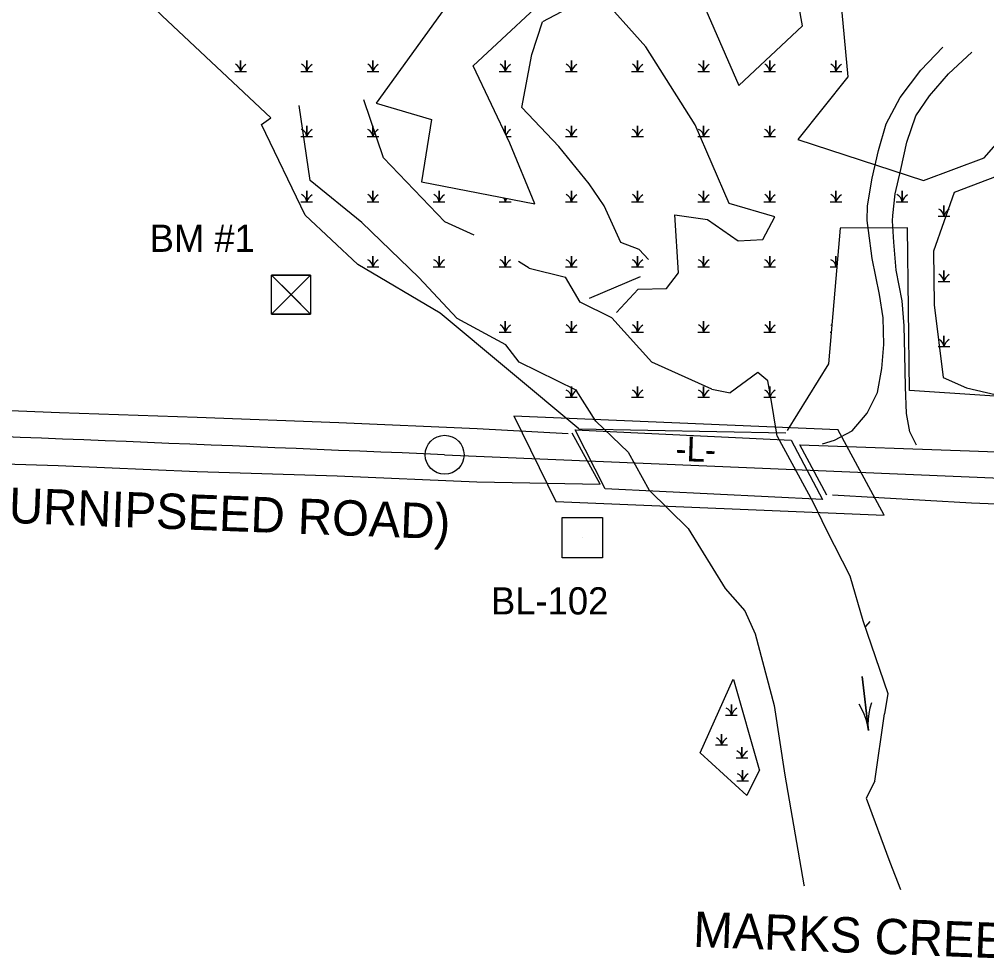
# Model space of a CAD drawing. Extents: x 2169223 to 2172151, y 723262 to 725175.
# Drawn here: x 2170758.3 to 2171113.8, y 723889.2 to 724234.9 of the extents above; entities that cross this region are included whole.
import ezdxf

# ---------------------------------------------------------------- set-up
doc = ezdxf.new("R2010")
doc.units = 0
for name, color, linetype in [('COGO Default Chain', 7, 'Continuous'), ('CTL Bench Mark CELL', 7, 'Continuous'), ('CTL Bench Mark Text', 7, 'Continuous'), ('CTL Supplemental Horizontal and Vertical CELL', 7, 'Continuous'), ('CTL Supplemental Horizontal and Vertical Text', 7, 'Continuous'), ('Default', 7, 'Continuous'), ('Exist Hydro Jurisdictional Stream or Body of Water', 7, 'Continuous'), ('Exist Hydro Pool or Reservoir', 7, 'Continuous'), ('Exist Hydro River Flow Arrow CELL', 7, 'Continuous'), ('Exist Roads EOP', 7, 'Continuous'), ('Exist Roads EOP Other', 7, 'Continuous'), ('Exist Structure Major Deck Tunnel Box Culvert', 7, 'Continuous'), ('Old_Level_12', 7, 'Continuous'), ('Prop Horizontal Alignment', 7, 'Continuous'), ('Prop Horizontal Alignment Direction Label', 7, 'Continuous'), ('Prop Horizontal Alignment Station Label', 7, 'Continuous')]:
    doc.layers.add(name, color=color, linetype=linetype)

# ---------------------------------------------------------------- blocks, each defined once
blk = doc.blocks.new('EXIST HYDRO RIVER FLOW ARROW')
at = {"layer": 'Exist Hydro River Flow Arrow CELL'}
blk.add_line((0, 0), (0, 0), dxfattribs=at)
blk.add_lwpolyline([(0, 0.04575), (0.03775, 0.03), (0.07725, 0.01725), (0.118, 0.00775), (0.159, 0.0015), (0.2, 0), (-0.2, 0), (0.2, 0), (0.159, -0.0015), (0.118, -0.00775), (0.07725, -0.01725), (0.03775, -0.03), (0, -0.04575)], dxfattribs=at)
blk = doc.blocks.new('Exist Hydro Swamp or Marsh')
at = {"layer": 'Default'}
blk.add_line((0, 0), (0, 0), dxfattribs=at)
blk.add_lwpolyline([(-0.043, -0.0357), (0, -0.0357), (0, 0.0432), (0, -0.0357), (0.043, -0.0357)], dxfattribs=at)
for centre, radius, start, end in [((-0.0613, -0.0401), 0.0615, 4.14034, 67.53497), ((0.0912, -0.066), 0.0961, 122.12745, 161.62219)]:
    blk.add_arc(centre, radius, start, end, dxfattribs=at)
blk = doc.blocks.new('CTL BENCH MARK')
at = {"layer": 'CTL Bench Mark CELL'}
blk.add_line((0, 0), (0, 0), dxfattribs=at)
blk.add_lwpolyline([(-0.072, 0.07175), (0.07175, 0.07175), (0.07175, -0.072), (-0.072, -0.072)], close=True, dxfattribs=at)
for points in [[(0.07175, 0.07175), (-0.072, -0.072), (-0.000125, -0.000125), (0.07175, -0.072), (-0.072, 0.07175)], [(-0.000125, -0.000125), (0.07175, 0.07175), (-0.072, 0.07175), (-0.000125, -0.000125)], [(-0.000125, -0.000125), (-0.072, -0.072), (0.07175, -0.072), (-0.000125, -0.000125)]]:
    blk.add_lwpolyline(points, dxfattribs=at)
blk = doc.blocks.new('CTL SUPPLEMENTAL HORIZONTAL AND VERTICAL')
at = {"layer": 'CTL Supplemental Horizontal and Vertical CELL'}
blk.add_line((0, 0), (0, 0), dxfattribs=at)
blk.add_lwpolyline([(-0.0735, 0.074), (0.07475, 0.074), (0.07475, -0.0745), (-0.0735, -0.0745)], close=True, dxfattribs=at)

msp = doc.modelspace()

# ---------------------------------------------------------------- linework, layer by layer
at = {"layer": 'COGO Default Chain'}
msp.add_lwpolyline([(2171039.94, 724084.11), (2171039.94, 724084.11), (2171039.94, 724084.11), (2171039.94, 724084.11), (2171039.94, 724084.11)], dxfattribs=at)
at = {"layer": 'Default'}
for p, q in [((2170940.05, 724089.16), (2171059.1, 724084.14)), ((2170940.05, 724089.16), (2170955.48, 724057.65)), ((2170964, 724084.29), (2171040, 724082.92)), ((2171076.21, 724052.56), (2171059.1, 724084.14)), ((2170955.48, 724057.65), (2171076.21, 724052.56)), ((2171020.86, 723992.13), (2171020.86, 723992.13)), ((2171030.33, 723958.99), (2171020.86, 723992.13))]:
    msp.add_line(p, q, dxfattribs=at)
for points in [[(2171646.71, 724409.08), (2171639.12, 724404.07), (2171615.95, 724359.66), (2171585.14, 724346.96), (2171572.27, 724330.12), (2171541.38, 724278.6), (2171494.05, 724272.59), (2171450.52, 724247.37), (2171445.92, 724243.67), (2171427.74, 724238.82), (2171406.38, 724186.3), (2171401.13, 724168.54), (2171393.3, 724167.45), (2171368.95, 724149.15), (2171363.45, 724127.38), (2171338.31, 724101.83), (2171299.81, 724093.74), (2171257.11, 724087.08), (2171085.47, 724098.48), (2171084.69, 724158.24), (2171059.94, 724158.08), (2171055.72, 724108.27), (2171040.51, 724083.75)], [(2170969.77, 724384.57), (2170964.6, 724352.67), (2170972.04, 724333.24), (2170983.7, 724287.77), (2170949.07, 724287.96), (2170925.23, 724253.71), (2170889.53, 724203.99), (2170909.76, 724198.04), (2170906.17, 724175.12), (2170947.8, 724166.99), (2170938.58, 724189.31), (2170925.06, 724217.79), (2170958.31, 724248.78), (2170980.13, 724250.58), (2170999.41, 724264.35), (2171022.73, 724210.59), (2171046.16, 724232.49), (2171037.9, 724278.23), (2171056.23, 724284.73), (2171062.81, 724213.77), (2171044.44, 724190.74), (2171090.65, 724175.58), (2171112.89, 724183.96), (2171129.39, 724202.76)], [(2170964, 724084.29), (2170912.98, 724126.85), (2170882.79, 724144.74), (2170863.38, 724162.92), (2170847.33, 724196.18), (2170850.8, 724198.69), (2170810.88, 724236.14), (2170789.38, 724258.53), (2170787.06, 724316.72), (2170767.72, 724349.95)], [(2170837.48, 724215.73), (2170839.63, 724215.73), (2170839.63, 724219.67), (2170839.63, 724215.73), (2170841.78, 724215.73)], [(2170861.8, 724215.73), (2170863.95, 724215.73), (2170863.95, 724219.67), (2170863.95, 724215.73), (2170866.1, 724215.73)], [(2170886.11, 724215.73), (2170888.26, 724215.73), (2170888.26, 724219.67), (2170888.26, 724215.73), (2170890.41, 724215.73)], [(2170934.73, 724215.73), (2170936.88, 724215.73), (2170936.88, 724219.67), (2170936.88, 724215.73), (2170939.03, 724215.73)], [(2170959.05, 724215.73), (2170961.2, 724215.73), (2170961.2, 724219.67), (2170961.2, 724215.73), (2170963.35, 724215.73)], [(2170983.36, 724215.73), (2170985.51, 724215.73), (2170985.51, 724219.67), (2170985.51, 724215.73), (2170987.66, 724215.73)], [(2171007.67, 724215.73), (2171009.82, 724215.73), (2171009.82, 724219.67), (2171009.82, 724215.73), (2171011.97, 724215.73)], [(2171031.98, 724215.73), (2171034.13, 724215.73), (2171034.13, 724219.67), (2171034.13, 724215.73), (2171036.28, 724215.73)], [(2171056.3, 724215.73), (2171058.45, 724215.73), (2171058.45, 724219.67), (2171058.45, 724215.73), (2171060.6, 724215.73)], [(2170861.8, 724191.78), (2170863.95, 724191.78), (2170863.95, 724195.72), (2170863.95, 724191.78), (2170866.1, 724191.78)], [(2170886.11, 724191.78), (2170888.26, 724191.78), (2170888.26, 724195.72), (2170888.26, 724191.78), (2170890.41, 724191.78)], [(2170936.88, 724192.89), (2170936.88, 724195.72), (2170936.88, 724192.89)], [(2170959.05, 724191.78), (2170961.2, 724191.78), (2170961.2, 724195.72), (2170961.2, 724191.78), (2170963.35, 724191.78)], [(2170983.36, 724191.78), (2170985.51, 724191.78), (2170985.51, 724195.72), (2170985.51, 724191.78), (2170987.66, 724191.78)], [(2171007.67, 724191.78), (2171009.82, 724191.78), (2171009.82, 724195.72), (2171009.82, 724191.78), (2171011.97, 724191.78)], [(2171031.98, 724191.78), (2171034.13, 724191.78), (2171034.13, 724195.72), (2171034.13, 724191.78), (2171036.28, 724191.78)], [(2170937.41, 724191.78), (2170939.03, 724191.78)], [(2170861.8, 724167.83), (2170863.95, 724167.83), (2170863.95, 724171.77), (2170863.95, 724167.83), (2170866.1, 724167.83)], [(2170886.11, 724167.83), (2170888.26, 724167.83), (2170888.26, 724171.77), (2170888.26, 724167.83), (2170890.41, 724167.83)], [(2170910.42, 724167.83), (2170912.57, 724167.83), (2170912.57, 724171.77), (2170912.57, 724167.83), (2170914.72, 724167.83)], [(2170959.05, 724167.83), (2170961.2, 724167.83), (2170961.2, 724171.77), (2170961.2, 724167.83), (2170963.35, 724167.83)], [(2170983.36, 724167.83), (2170985.51, 724167.83), (2170985.51, 724171.77), (2170985.51, 724167.83), (2170987.66, 724167.83)], [(2171007.67, 724167.83), (2171009.82, 724167.83), (2171009.82, 724171.77), (2171009.82, 724167.83), (2171011.97, 724167.83)], [(2171031.98, 724167.83), (2171034.13, 724167.83), (2171034.13, 724171.77), (2171034.13, 724167.83), (2171036.28, 724167.83)], [(2171056.3, 724167.83), (2171058.45, 724167.83), (2171058.45, 724171.77), (2171058.45, 724167.83), (2171060.6, 724167.83)], [(2171080.61, 724167.83), (2171082.76, 724167.83), (2171082.76, 724171.77), (2171082.76, 724167.83), (2171084.91, 724167.83)], [(2170934.73, 724167.83), (2170936.88, 724167.83), (2170936.88, 724169.12)], [(2170936.88, 724169.12), (2170936.88, 724167.83), (2170939.03, 724167.83)], [(2171095.94, 724162.5), (2171098.09, 724162.5), (2171098.09, 724166.45), (2171098.09, 724162.5), (2171100.24, 724162.5)], [(2170886.11, 724143.88), (2170888.26, 724143.88), (2170888.26, 724147.82), (2170888.26, 724143.88), (2170890.41, 724143.88)], [(2170910.42, 724143.88), (2170912.57, 724143.88), (2170912.57, 724147.82), (2170912.57, 724143.88), (2170914.72, 724143.88)], [(2170934.73, 724143.88), (2170936.88, 724143.88), (2170936.88, 724147.82), (2170936.88, 724143.88), (2170939.03, 724143.88)], [(2170959.05, 724143.88), (2170961.2, 724143.88), (2170961.2, 724147.82), (2170961.2, 724143.88), (2170963.35, 724143.88)], [(2170983.36, 724143.88), (2170985.51, 724143.88), (2170985.51, 724147.82), (2170985.51, 724143.88), (2170987.66, 724143.88)], [(2171007.67, 724143.88), (2171009.82, 724143.88), (2171009.82, 724147.82), (2171009.82, 724143.88), (2171011.97, 724143.88)], [(2171031.98, 724143.88), (2171034.13, 724143.88), (2171034.13, 724147.82), (2171034.13, 724143.88), (2171036.28, 724143.88)], [(2171056.3, 724143.88), (2171058.45, 724143.88), (2171058.45, 724147.82), (2171058.45, 724143.88), (2171058.73, 724143.88)], [(2171095.94, 724138.55), (2171098.09, 724138.55), (2171098.09, 724142.5), (2171098.09, 724138.55), (2171100.24, 724138.55)], [(2170934.73, 724119.93), (2170936.88, 724119.93), (2170936.88, 724123.87), (2170936.88, 724119.93), (2170939.03, 724119.93)], [(2170959.05, 724119.93), (2170961.2, 724119.93), (2170961.2, 724123.87), (2170961.2, 724119.93), (2170963.35, 724119.93)], [(2170983.36, 724119.93), (2170985.51, 724119.93), (2170985.51, 724123.87), (2170985.51, 724119.93), (2170987.66, 724119.93)], [(2171007.67, 724119.93), (2171009.82, 724119.93), (2171009.82, 724123.87), (2171009.82, 724119.93), (2171011.97, 724119.93)], [(2171031.98, 724119.93), (2171034.13, 724119.93), (2171034.13, 724123.87), (2171034.13, 724119.93), (2171036.28, 724119.93)], [(2171056.3, 724119.93), (2171056.71, 724119.93)], [(2171095.94, 724114.6), (2171098.09, 724114.6), (2171098.09, 724118.55), (2171098.09, 724114.6), (2171100.24, 724114.6)], [(2170959.05, 724095.98), (2170961.2, 724095.98), (2170961.2, 724099.92), (2170961.2, 724095.98), (2170963.35, 724095.98)], [(2170983.36, 724095.98), (2170985.51, 724095.98), (2170985.51, 724099.92), (2170985.51, 724095.98), (2170987.66, 724095.98)], [(2171007.67, 724095.98), (2171009.82, 724095.98), (2171009.82, 724099.92), (2171009.82, 724095.98), (2171011.97, 724095.98)], [(2171031.98, 724095.98), (2171034.13, 724095.98), (2171034.13, 724099.92), (2171034.13, 724095.98), (2171036.28, 724095.98)], [(2171030.33, 723958.99), (2171025.69, 723949.62), (2171008.55, 723965.23), (2171020.62, 723992.37)]]:
    msp.add_lwpolyline(points, dxfattribs=at)
for centre, radius, start, end in [((2170836.57, 724215.51), 3.07, 4.1403, 67.535), ((2170844.19, 724214.21), 4.81, 122.1274, 161.6222), ((2170860.88, 724215.51), 3.07, 4.1403, 67.535), ((2170868.51, 724214.21), 4.81, 122.1274, 161.6222), ((2170885.19, 724215.51), 3.07, 4.1403, 67.535), ((2170892.82, 724214.21), 4.81, 122.1274, 161.6222), ((2170933.82, 724215.51), 3.07, 4.1403, 67.535), ((2170941.44, 724214.21), 4.81, 122.1274, 161.6222), ((2170958.13, 724215.51), 3.07, 4.1403, 67.535), ((2170965.76, 724214.21), 4.81, 122.1274, 161.6222), ((2170982.44, 724215.51), 3.07, 4.1403, 67.535), ((2170990.07, 724214.21), 4.81, 122.1274, 161.6222), ((2171006.76, 724215.51), 3.07, 4.1403, 67.535), ((2171014.38, 724214.21), 4.81, 122.1274, 161.6222), ((2171031.07, 724215.51), 3.07, 4.1403, 67.535), ((2171038.69, 724214.21), 4.81, 122.1274, 161.6222), ((2171055.38, 724215.51), 3.07, 4.1403, 67.535), ((2171063.01, 724214.21), 4.81, 122.1274, 161.6222), ((2170860.88, 724191.56), 3.07, 4.1403, 67.535), ((2170868.51, 724190.26), 4.81, 122.1274, 161.6222), ((2170885.19, 724191.56), 3.07, 4.1403, 67.535), ((2170892.82, 724190.26), 4.81, 122.1274, 161.6222), ((2170941.44, 724190.26), 4.81, 122.1274, 153.947), ((2170958.13, 724191.56), 3.07, 4.1403, 67.535), ((2170965.76, 724190.26), 4.81, 122.1274, 161.6222), ((2170982.44, 724191.56), 3.07, 4.1403, 67.535), ((2170990.07, 724190.26), 4.81, 122.1274, 161.6222), ((2171006.76, 724191.56), 3.07, 4.1403, 67.535), ((2171014.38, 724190.26), 4.81, 122.1274, 161.6222), ((2171031.07, 724191.56), 3.07, 4.1403, 67.535), ((2171038.69, 724190.26), 4.81, 122.1274, 161.6222), ((2170860.88, 724167.61), 3.07, 4.1403, 67.535), ((2170868.51, 724166.31), 4.81, 122.1274, 161.6222), ((2170885.19, 724167.61), 3.07, 4.1403, 67.535), ((2170892.82, 724166.31), 4.81, 122.1274, 161.6222), ((2170909.51, 724167.61), 3.07, 4.1403, 67.535), ((2170917.13, 724166.31), 4.81, 122.1274, 161.6222), ((2170958.13, 724167.61), 3.07, 4.1403, 67.535), ((2170965.76, 724166.31), 4.81, 122.1274, 161.6222), ((2170982.44, 724167.61), 3.07, 4.1403, 67.535), ((2170990.07, 724166.31), 4.81, 122.1274, 161.6222), ((2171006.76, 724167.61), 3.07, 4.1403, 67.535), ((2171014.38, 724166.31), 4.81, 122.1274, 161.6222), ((2171031.07, 724167.61), 3.07, 4.1403, 67.535), ((2171038.69, 724166.31), 4.81, 122.1274, 161.6222), ((2171055.38, 724167.61), 3.07, 4.1403, 67.535), ((2171063.01, 724166.31), 4.81, 122.1274, 161.6222), ((2171079.69, 724167.61), 3.07, 4.1403, 67.535), ((2171087.32, 724166.31), 4.81, 122.1274, 161.6222), ((2170933.82, 724167.61), 3.07, 4.1403, 31.3423), ((2170941.44, 724166.31), 4.81, 145.9165, 161.6222), ((2171095.02, 724162.28), 3.07, 4.1403, 67.535), ((2171102.65, 724160.99), 4.81, 122.1274, 161.6222), ((2170885.19, 724143.66), 3.07, 4.1403, 67.535), ((2170892.82, 724142.36), 4.81, 122.1274, 161.6222), ((2170909.51, 724143.66), 3.07, 4.1403, 67.535), ((2170917.13, 724142.36), 4.81, 122.1274, 161.6222), ((2170933.82, 724143.66), 3.07, 4.1403, 67.535), ((2170941.44, 724142.36), 4.81, 122.1274, 161.6222), ((2170958.13, 724143.66), 3.07, 4.1403, 67.535), ((2170965.76, 724142.36), 4.81, 122.1274, 161.6222), ((2170982.44, 724143.66), 3.07, 4.1403, 67.535), ((2170990.07, 724142.36), 4.81, 122.1274, 161.6222), ((2171006.76, 724143.66), 3.07, 4.1403, 67.535), ((2171014.38, 724142.36), 4.81, 122.1274, 161.6222), ((2171031.07, 724143.66), 3.07, 4.1403, 67.535), ((2171038.69, 724142.36), 4.81, 122.1274, 161.6222), ((2171055.38, 724143.66), 3.07, 4.1403, 67.535), ((2171063.01, 724142.36), 4.81, 151.0471, 161.6222), ((2171095.02, 724138.33), 3.07, 4.1403, 67.535), ((2171102.65, 724137.04), 4.81, 122.1274, 161.6222), ((2170933.82, 724119.71), 3.07, 4.1403, 67.535), ((2170941.44, 724118.41), 4.81, 122.1274, 161.6222), ((2170958.13, 724119.71), 3.07, 4.1403, 67.535), ((2170965.76, 724118.41), 4.81, 122.1274, 161.6222), ((2170982.44, 724119.71), 3.07, 4.1403, 67.535), ((2170990.07, 724118.41), 4.81, 122.1274, 161.6222), ((2171006.76, 724119.71), 3.07, 4.1403, 67.535), ((2171014.38, 724118.41), 4.81, 122.1274, 161.6222), ((2171031.07, 724119.71), 3.07, 4.1403, 67.535), ((2171038.69, 724118.41), 4.81, 122.1274, 161.6222), ((2171055.38, 724119.71), 3.07, 60.0867, 67.535), ((2171095.02, 724114.38), 3.07, 4.1403, 67.535), ((2171102.65, 724113.09), 4.81, 122.1274, 161.6222), ((2170958.13, 724095.76), 3.07, 4.1403, 67.535), ((2170965.76, 724094.46), 4.81, 122.1274, 161.6222), ((2170982.44, 724095.76), 3.07, 4.1403, 67.535), ((2170990.07, 724094.46), 4.81, 122.1274, 161.6222), ((2171006.76, 724095.76), 3.07, 4.1403, 67.535), ((2171014.38, 724094.46), 4.81, 122.1274, 161.6222), ((2171031.07, 724095.76), 3.07, 4.1403, 67.535), ((2171038.69, 724094.46), 4.81, 122.1274, 161.6222)]:
    msp.add_arc(centre, radius, start, end, dxfattribs=at)
at = {"layer": 'Exist Hydro Jurisdictional Stream or Body of Water'}
for p, q in [((2170946.63, 724221.96), (2170950.55, 724233.91)), ((2170884.26, 724160.19), (2170905.17, 724139.91)), ((2170945.66, 724143.34), (2170959.03, 724140.13)), ((2171012.86, 724098.98), (2171019.61, 724097.56)), ((2171036.82, 724081.59), (2171050, 724057.51)), ((2171024.93, 724017.5), (2171028.8, 724008.93)), ((2171072.73, 723954.84), (2171076.23, 723979.59))]:
    msp.add_line(p, q, dxfattribs=at)
for points in [[(2170884.26, 724160.19), (2170865.24, 724175.63), (2170861.21, 724203.22)], [(2170925.53, 724155.5), (2170914.75, 724160.48), (2170892.18, 724183.92), (2170884.97, 724205.32)], [(2170945.66, 724143.34), (2170941.74, 724145.88)], [(2170970.19, 724087.2), (2170963.02, 724098.54), (2170942.04, 724108.86), (2170937.11, 724115.2), (2170919.25, 724124.89), (2170905.17, 724139.91)], [(2170976.02, 724125.16), (2170964.39, 724130.86), (2170959.03, 724140.13)], [(2171012.86, 724098.98), (2170990.81, 724108.82), (2170976.02, 724125.16)], [(2171036.82, 724081.59), (2171034.37, 724096.6), (2171033.44, 724101.99), (2171029.74, 724104.99), (2171019.61, 724097.56)], [(2170970.19, 724087.2), (2170982.1, 724075.71), (2170989.83, 724061.83)], [(2170989.83, 724061.83), (2171004.11, 724047.68), (2171017.77, 724025.7), (2171024.93, 724017.5)], [(2171050, 724057.51), (2171054.91, 724047.11), (2171063.58, 724030.3), (2171068.32, 724013.89), (2171077.53, 723987.03), (2171076.23, 723979.59)], [(2171028.8, 724008.93), (2171035.74, 723982.68), (2171039.7, 723957.05), (2171046.58, 723916.77), (2171046.79, 723916.38)], [(2171072.73, 723954.84), (2171069.59, 723948.54), (2171078.18, 723925.11), (2171082.13, 723915.06)]]:
    msp.add_lwpolyline(points, dxfattribs=at)
at = {"layer": 'Exist Hydro Pool or Reservoir'}
msp.add_line((2170985.7, 724135.65), (2170996.18, 724135.93), dxfattribs=at)
for points in [[(2171176.9, 724258.74), (2171160.18, 724236.17), (2171143.74, 724205.7), (2171126.42, 724180.58), (2171101.94, 724171.18), (2171094.33, 724149.7), (2171094.48, 724129.88), (2171097.83, 724103.15), (2171106.41, 724099.4), (2171122.68, 724095.66), (2171174.27, 724094.52), (2171208.02, 724090.36), (2171237.1, 724086.39), (2171260.39, 724102.8), (2171273.88, 724116.96), (2171289.64, 724106.85), (2171299.45, 724105.65)], [(2170996.18, 724135.93), (2171000.52, 724141.72), (2170999.2, 724162.98), (2171011.21, 724161.27), (2171022.5, 724153.5), (2171031.55, 724153.95), (2171035.93, 724162.28), (2171019.24, 724167.2), (2171006.76, 724196.12), (2170988.58, 724224.72), (2170970.77, 724244.76), (2170950.55, 724233.91)], [(2170989.5, 724146.62), (2170986.13, 724150.21), (2170979.44, 724152.82), (2170973.21, 724166.27), (2170967.72, 724174.45), (2170956.54, 724188.09), (2170943.06, 724202.49), (2170946.63, 724221.96)], [(2170986.43, 724140.17), (2170967.74, 724132.29)], [(2170977.84, 724127.12), (2170985.7, 724135.65)]]:
    msp.add_lwpolyline(points, dxfattribs=at)
at = {"layer": 'Exist Roads EOP'}
for points in [[(2170401.86, 724104.27), (2170452.98, 724102.56), (2170508.15, 724100.65), (2170561.36, 724098.56), (2170615.16, 724096.64), (2170668.07, 724094.68), (2170721.74, 724092.4), (2170773.08, 724090.36), (2170823.75, 724088.57), (2170875.78, 724086.65), (2170926.55, 724084.44), (2170960.03, 724082.65)], [(2170401.4, 724084.29), (2170452.99, 724082.62), (2170507.21, 724080.6), (2170561, 724078.45), (2170614.98, 724076.67), (2170668.55, 724074.62), (2170720.86, 724072.47), (2170772.59, 724070.81), (2170823.72, 724068.64), (2170875.12, 724067.11), (2170926.51, 724064.84), (2170971.76, 724064), (2170961.56, 724082.7)], [(2171055.09, 724059.99), (2171045.17, 724078.4), (2171107.52, 724076.3), (2171160.05, 724074.32)], [(2171057.15, 724060.04), (2171108.26, 724057.19), (2171159.83, 724055.04)]]:
    msp.add_lwpolyline(points, dxfattribs=at)
at = {"layer": 'Exist Roads EOP Other'}
for points in [[(2171053.45, 724078.85), (2171057.86, 724080.2), (2171064.36, 724083.61), (2171069.91, 724090.11), (2171073.71, 724097.65), (2171075.35, 724106.47), (2171076.06, 724115.37), (2171075.74, 724125.15), (2171074.42, 724133.75), (2171071.75, 724146.91), (2171070.38, 724157.25), (2171069.91, 724160.86), (2171070.01, 724166.26), (2171071.79, 724176.53), (2171074.04, 724186.64), (2171076.9, 724196.49), (2171082.06, 724206.09), (2171089.57, 724216.15), (2171097.76, 724224.58)], [(2171087.98, 724078.33), (2171085.57, 724083.23), (2171084.36, 724089.92), (2171083.96, 724099.79), (2171083.78, 724111.64), (2171083.46, 724122.19), (2171082.71, 724131.4), (2171080.61, 724142.71), (2171079.74, 724152.9), (2171079.24, 724160.8), (2171079.28, 724162.77), (2171080.18, 724170.7), (2171082.29, 724179.62), (2171084.53, 724189.68), (2171087.84, 724199.4), (2171092.85, 724206.76), (2171099.85, 724214.8), (2171108.31, 724222.84)]]:
    msp.add_lwpolyline(points, dxfattribs=at)
at = {"layer": 'Exist Structure Major Deck Tunnel Box Culvert'}
msp.add_lwpolyline([(2171042, 724080.19), (2171053.5, 724058.36), (2170973.59, 724062.32), (2170962.64, 724083.94), (2171042, 724080.19)], dxfattribs=at)
at = {"layer": 'Old_Level_12'}
msp.add_lwpolyline([(2171069.47, 724011.72), (2171070.98, 724013.54)], dxfattribs=at)
at = {"layer": 'Prop Horizontal Alignment'}
msp.add_line((2170914.62, 724074.81), (2171360.17, 724056), dxfattribs=at)
msp.add_arc((2168445.99, 665601.01), 58525.88, 87.5825428, 88.0715445, dxfattribs=at)
at = {"layer": 'Prop Horizontal Alignment Station Label'}
msp.add_circle((2170914.62, 724074.81), 7.15, dxfattribs=at)

# ---------------------------------------------------------------- block references
at = {"layer": 'CTL Bench Mark CELL', "xscale": 100, "yscale": 100}
msp.add_blockref('CTL BENCH MARK', (2170858.2, 724133.67), dxfattribs=at)
at = {"layer": 'CTL Supplemental Horizontal and Vertical CELL', "xscale": 100, "yscale": 100}
msp.add_blockref('CTL SUPPLEMENTAL HORIZONTAL AND VERTICAL', (2170965.13, 724044.36), dxfattribs=at)
at = {"layer": 'Default', "xscale": 50, "yscale": 50}
for p in [(2171020.03, 723980.86), (2171016.38, 723969.93), (2171023.9, 723965.15), (2171024.12, 723956.72)]:
    msp.add_blockref('Exist Hydro Swamp or Marsh', p, dxfattribs=at)
at = {"layer": 'Exist Hydro River Flow Arrow CELL', "xscale": 50, "yscale": 49.99999999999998, "rotation": -83.565045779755}
msp.add_blockref('EXIST HYDRO RIVER FLOW ARROW', (2171069.23, 723983.4), dxfattribs=at)

# ---------------------------------------------------------------- texts
at = {"layer": 'CTL Bench Mark Text'}
msp.add_text('BM #1', height=10, dxfattribs=at).set_placement((2170806.26, 724149.39))
at = {"layer": 'CTL Supplemental Horizontal and Vertical Text'}
msp.add_text('BL-102', height=10, rotation=0, dxfattribs=at).set_placement((2170931.67, 724016.1))
at = {"layer": 'Default'}
for s, p in [('-L- SR 2507 (TURNIPSEED ROAD)', (2170639.44, 724054.07)), ('MARKS CREEK', (2171005.83, 723893.95))]:
    msp.add_text(s, height=13, rotation=357.8574, dxfattribs=at).set_placement(p)
at = {"layer": 'Prop Horizontal Alignment Direction Label'}
msp.add_text('-L-', height=9.082, rotation=358.0715, dxfattribs=at).set_placement((2170999.39, 724072.56))

doc.saveas('drawing.dxf')
